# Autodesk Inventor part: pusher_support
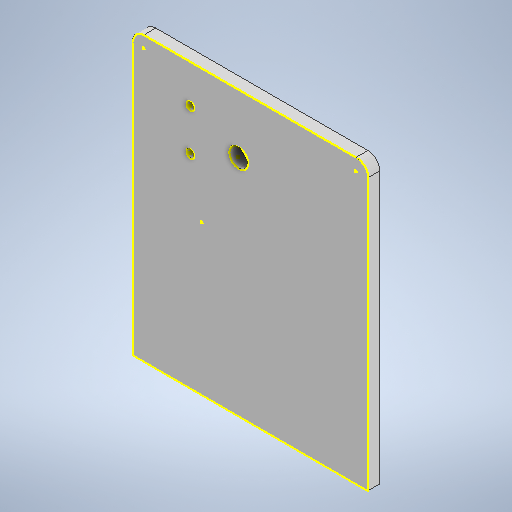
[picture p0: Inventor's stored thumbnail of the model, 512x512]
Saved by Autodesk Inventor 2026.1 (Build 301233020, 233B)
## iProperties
Created: 2026-10
Part Number: pusher_support
Material: Generic
Document SubType Name: Modeling
Designer: alolo
Density: 1 g/cm^3
Appearance: Default
Author: alolo
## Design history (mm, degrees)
sketch "Sketch1"
  geometry: L1 (0, 0)-(41, 0); L2 (41, 0)-(41, 21); L3 (41, 21)-(0, 21); L4 (0, 21)-(0, 0); L5 (20.5, 0)-(20.5, 21); L6 (-29.5, 56.5)-(70.5, 56.5); L7 (70.5, 56.5)-(70.5, -43.5); L8 (70.5, -43.5)-(-29.5, -43.5); L9 (-29.5, -43.5)-(-29.5, 56.5); L10 (-29.5, -43.5)-(70.5, -43.5); L11 (70.5, -43.5)-(70.5, -63.5); L12 (70.5, -63.5)-(-29.5, -63.5); L13 (-29.5, -63.5)-(-29.5, -43.5); C1 r 2.2 at (-5, 6.5); C2 r 2.2 at (-5, 15.5); C3 r 2.2 at (46, 6.5); C4 r 2.2 at (46, 15.5); 2 further points
  constraints: 26 end point, 6 parallel, 4 centre point, 3 horizontal, 3 midpoint, 3 perpendicular, 2 symmetric about line, 2 vertical alignment, 2 other
  dimensions: "d0" = 41 distance of L3.end L2.end; "d1" = 4.4 diameter of C1; "d2" = 21 distance of L1.end L2.end; "d3" = 5 distance from line of L4 C1.centre; "d4" = 14.5 distance from line of L3 C1.centre; "d5" = 4.4 diameter of C2; "d6" = 5.5 distance from line of L3 C2.centre; "d7" = 100 distance of L6.end L7.end; "d8" = 43.5 distance between parallel lines of L1 L8; "d9" = 100 distance of L6.start L6.end; "d33" = 100 distance of L11.end L12.end; "d34" = 20 distance of L10.end L11.end
extrude "Extrusion1" new body sketch "Sketch1" distance "d10" = 5 (= wood_thickness); taper "d11" = 0 deg
sketch "Sketch5"
  geometry: L1 (70.5, -63.5)-(70.5, 56.5) reference; L2 (70.5, 56.5)-(-29.5, 56.5) reference; L3 (-29.5, 56.5)-(-29.5, -63.5) reference; L4 (-29.5, -63.5)-(70.5, -63.5) reference; C1 r 4 at (15.5, 31.5); 2 further points
  constraints: 1 centre point, 1 midpoint
  dimensions: "d35" = 8 diameter of C1; "d37" = 55 distance from line of L1 C1.centre; "d40" = 25 distance from line of L2 C1.centre
  node "Projected Loop1"
fillet "Fillet1" dims "d36" = 5
extrude "Extrusion2" cut sketch "Sketch5" distance "d38" = 5 (= wood_thickness); taper "d39" = 0 deg
sketch "Sketch6"
  geometry: L1 (-29.5, 51.5)-(-29.5, -63.5) reference; L2 (-29.5, -63.5)-(70.5, -63.5) reference; L3 (70.5, -63.5)-(70.5, 51.5) reference; L4 (65.5, 56.5)-(-24.5, 56.5) reference; C1 r 4 at (15.5, 31.5) reference; A1 r 5 centre (-24.5, 51.5) between (-24.5, 56.5) and (-29.5, 51.5) reference; A2 r 5 centre (65.5, 51.5) between (70.5, 51.5) and (65.5, 56.5) reference; 1 further point
  node "Projected Loop2"
sketch "Sketch7"
  geometry: 2 further points
hole "Hole4" sketch "Sketch7" at (-5, 40.25), (-5, 22.75) diameter "d41" = 3.4; stored, may be unused: countersink angle "d45" = 90 deg, drill point angle "d47" = 0 deg; dims "d42" = 6, "d43" = 4, "d44" = 2, "d46" = 8
sketch "Sketch9"
  geometry: L1 (70.5, 51.5)-(70.5, -63.5) reference; L2 (70.5, -63.5)-(-29.5, -63.5) reference; L3 (-29.5, -63.5)-(-29.5, 51.5) reference; L4 (-24.5, 56.5)-(65.5, 56.5) reference; C1 r 4 at (15.5, 31.5) reference; C2 r 1.7 at (-5, 22.75) reference; C3 r 1.7 at (-5, 40.25) reference; A1 r 5 centre (65.5, 51.5) between (70.5, 51.5) and (65.5, 56.5) reference; A2 r 5 centre (-24.5, 51.5) between (-24.5, 56.5) and (-29.5, 51.5) reference; 1 further point
  node "Project Cut Edges2"
body "Solid1"
other parameters: "slide_length" = 195 [user parameter], "slide_angle" = 7 deg [user parameter], "slide_width" = 65 [user parameter], "wood_thickness" = 5 [user parameter; used in 2 equation terms], "aclyric_thickness" = 6 [user parameter]
